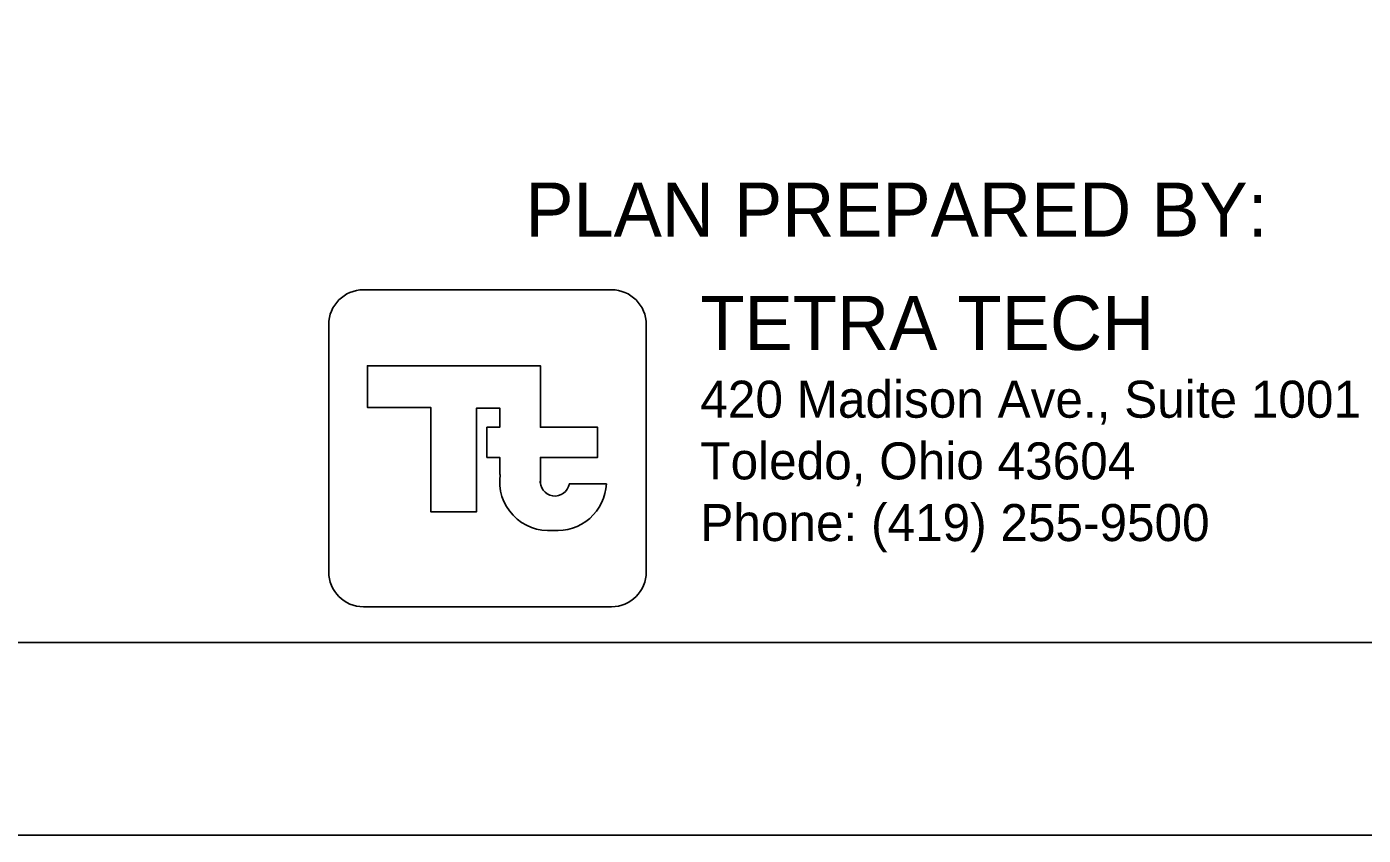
# Model space of a CAD drawing. Extents: x -8.3 to 42.1, y 0 to 22.
# Drawn here: x 2.32 to 5.785, y 0 to 2.097 of the extents above; entities that cross this region are included whole.
import ezdxf

# ---------------------------------------------------------------- set-up
doc = ezdxf.new("R2010")
doc.units = 0
for name, color, linetype in [('SH_Border', 7, 'Continuous'), ('SH_Cut_Line', 7, 'Continuous'), ('SH_Data', 7, 'Continuous'), ('SH_Text', 7, 'Continuous')]:
    doc.layers.add(name, color=color, linetype=linetype)

msp = doc.modelspace()

# ---------------------------------------------------------------- linework, layer by layer
at = {"layer": 'SH_Border'}
msp.add_lwpolyline([(1.5, 21.5), (33.5, 21.5), (33.5, 0.5), (1.5, 0.5)], close=True, dxfattribs=at)
at = {"layer": 'SH_Cut_Line'}
msp.add_lwpolyline([(0, 0), (34, 0), (34, 22), (0, 22)], close=True, dxfattribs=at)
at = {"layer": 'SH_Data'}
for points in [[(3.1929, 1.4149), (3.8357, 1.4149)], [(3.1028, 0.683), (3.1028, 1.3247)], [(3.9258, 1.3247), (3.9258, 0.683)], [(3.203, 1.218), (3.6516, 1.218), (3.6516, 1.0582), (3.7997, 1.0582), (3.7997, 0.9799), (3.6516, 0.9799), (3.6516, 0.9124)], [(3.6516, 0.9231), (3.6516, 0.9799), (3.7997, 0.9799), (3.7997, 1.0582), (3.6516, 1.0582), (3.6516, 1.218), (3.203, 1.218), (3.203, 1.1098), (3.367, 1.1098), (3.367, 0.8392), (3.486, 0.8392), (3.486, 1.1081), (3.5459, 1.1081), (3.5459, 1.0582), (3.5126, 1.0582), (3.5126, 0.9799), (3.5459, 0.9799), (3.5459, 0.9358), (3.5472, 0.9358)], [(3.8227, 0.9118), (3.7264, 0.9118)], [(3.8357, 0.5929), (3.1929, 0.5929)]]:
    msp.add_lwpolyline(points, dxfattribs=at)
for centre, radius, start, end in [((3.1929, 1.3247), 0.0902, 90, 180), ((3.8357, 1.3247), 0.0902, 360, 90), ((3.6736, 0.9178), 0.1277, 171.8856, 274.8323), ((3.6891, 0.9178), 0.0379, 171.8856, 350.9243), ((3.6951, 0.9178), 0.1277, 265.1677, 357.3201), ((3.1929, 0.683), 0.0902, 180, 270), ((3.8357, 0.683), 0.0902, 270, 360)]:
    msp.add_arc(centre, radius, start, end, dxfattribs=at)

# ---------------------------------------------------------------- texts
for s, height, p in [('TETRA TECH', 0.14019, (4.0662, 1.2589)), ('420 Madison Ave., Suite 1001', 0.096, (4.0662, 1.0831)), ('Toledo, Ohio 43604', 0.096, (4.0662, 0.9231)), ('Phone: (419) 255-9500', 0.096, (4.0662, 0.7631))]:
    msp.add_text(s, height=height, rotation=360, dxfattribs=at).set_placement(p)
at = {"layer": 'SH_Text'}
msp.add_text('PLAN PREPARED BY:', height=0.14, dxfattribs=at).set_placement((3.6125, 1.553))

doc.saveas('drawing.dxf')
